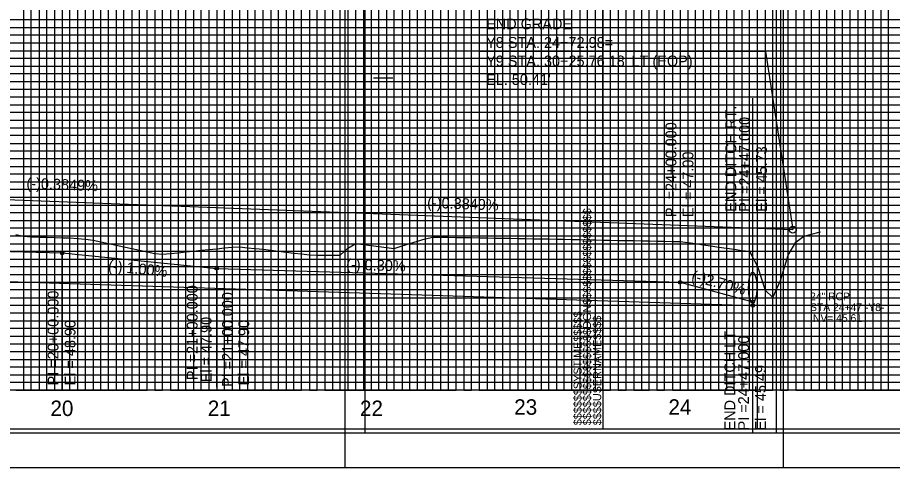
# Model space of a CAD drawing. Extents: x 2345490 to 2436403, y 465165 to 573888.
# Drawn here: x 2382738 to 2383304, y 540975 to 541266 of the extents above; entities that cross this region are included whole.
import ezdxf

# ---------------------------------------------------------------- set-up
doc = ezdxf.new("R2010")
doc.units = 0
for name, color, linetype in [('Exist Vertical Profile Horizontal Axis Label Major', 7, 'Continuous'), ('Old_Level_1', 7, 'Continuous'), ('Old_Level_18', 7, 'Continuous'), ('Old_Level_2', 7, 'Continuous'), ('Old_Level_3', 7, 'Continuous'), ('Old_Level_40', 7, 'Continuous'), ('Old_Level_41', 7, 'Continuous'), ('Old_Level_42', 7, 'Continuous'), ('Old_Level_43', 7, 'Continuous'), ('Old_Level_50', 7, 'Continuous'), ('Old_Level_51', 7, 'Continuous'), ('Old_Level_52', 7, 'Continuous')]:
    doc.layers.add(name, color=color, linetype=linetype)

msp = doc.modelspace()

# ---------------------------------------------------------------- linework, layer by layer
at = {"layer": 'Old_Level_1'}
for points in [[(2382736.7988, 541125.45291), (2382741.7988, 541124.31269), (2382746.7988, 541123.91261), (2382751.7988, 541123.78471), (2382756.7988, 541123.65566), (2382761.7988, 541123.52552), (2382766.7988, 541123.39433)], [(2382766.7988, 541123.39433), (2382771.7988, 541123.26218), (2382776.7988, 541122.90649), (2382781.7988, 541122.52221), (2382786.7988, 541121.84052), (2382791.7988, 541120.73783), (2382796.7988, 541119.63854), (2382801.7988, 541118.54315), (2382806.7988, 541117.45216), (2382811.7988, 541116.36605), (2382816.7988, 541115.28532), (2382821.7988, 541114.17672), (2382826.7988, 541113.07155), (2382831.7988, 541112.65207), (2382836.7988, 541113.14818), (2382841.7988, 541113.68281), (2382846.7988, 541114.21205), (2382851.7988, 541114.73272), (2382856.7988, 541115.2446), (2382861.7988, 541115.74744), (2382866.7988, 541116.24104), (2382871.7988, 541116.72515), (2382876.7988, 541117.19956), (2382881.7988, 541117.38911), (2382886.7988, 541116.88286), (2382891.7988, 541116.39226), (2382896.7988, 541115.91864), (2382901.7988, 541115.33093), (2382906.7988, 541114.69938), (2382911.7988, 541114.07598), (2382916.7988, 541113.461), (2382921.7988, 541112.85473), (2382926.7988, 541112.25743), (2382931.7988, 541112.11719), (2382936.7988, 541112.05292), (2382941.7988, 541111.9908), (2382946.7988, 541111.98307), (2382951.7988, 541116.65561), (2382956.7988, 541119.64421), (2382961.7988, 541119.01871), (2382966.7988, 541118.37196), (2382971.7988, 541117.70426), (2382976.7988, 541117.01592), (2382981.7988, 541116.38101), (2382986.7988, 541118.01227), (2382991.7988, 541119.61425), (2382996.7988, 541121.18623), (2383001.7988, 541122.7275), (2383006.7988, 541123.69866), (2383011.7988, 541123.71017), (2383016.7988, 541123.6775), (2383021.7988, 541123.60122), (2383026.7988, 541123.52237), (2383031.7988, 541123.441), (2383036.7988, 541123.35714), (2383041.7988, 541123.27083), (2383046.7988, 541123.1821), (2383051.7988, 541123.091), (2383056.7988, 541122.99758), (2383061.7988, 541122.90186), (2383066.7988, 541122.80938), (2383071.7988, 541122.72287), (2383076.7988, 541122.63529), (2383081.7988, 541122.54668), (2383086.7988, 541122.45707), (2383091.7988, 541122.35847), (2383096.7988, 541122.23957), (2383101.7988, 541122.13262), (2383106.7988, 541122.03737), (2383111.7988, 541121.94212), (2383116.7988, 541121.84688), (2383121.7988, 541121.75163), (2383126.7988, 541121.65638), (2383131.7988, 541121.56114), (2383136.7988, 541121.46589), (2383141.7988, 541121.37064), (2383146.7988, 541121.2754), (2383151.7988, 541121.18015), (2383156.7988, 541121.0849), (2383161.7988, 541120.98965), (2383166.7988, 541120.89441), (2383171.7988, 541120.24181), (2383176.7988, 541119.51729), (2383181.7988, 541118.79276), (2383186.7988, 541118.06824), (2383191.7988, 541117.34372), (2383196.7988, 541116.61919), (2383201.7988, 541115.89467), (2383206.7988, 541115.17015), (2383211.7988, 541114.57352), (2383216.7988, 541104.6758), (2383221.7988, 541089.28992), (2383226.7988, 541084.70339), (2383231.7988, 541095.7072), (2383236.7988, 541112.14277), (2383241.7988, 541120.4894), (2383246.7988, 541124.38886), (2383251.7988, 541125.6911), (2383256.7988, 541126.94345), (2383257.7788, 541127.17918)]]:
    msp.add_lwpolyline(points, dxfattribs=at)
at = {"layer": 'Old_Level_18'}
msp.add_line((2383116.79875, 540999.5045), (2383116.79875, 540999.5045), dxfattribs=at)
msp.add_line((2383116.79875, 540999.5045), (2383116.79875, 540999.5045), dxfattribs=at)
for points in [[(2383216.79875, 542049.5045), (2381716.79875, 542049.5045), (2381716.79875, 540999.5045), (2383216.79875, 540999.5045)], [(2384616.79875, 542049.5045), (2383116.79875, 542049.5045), (2383116.79875, 540999.5045), (2384616.79875, 540999.5045)]]:
    msp.add_lwpolyline(points, close=True, dxfattribs=at)
at = {"layer": 'Old_Level_2'}
for p, q in [((2383222.04055, 541243.91325), (2383036.88355, 541243.91325)), ((2383222.04055, 541243.91325), (2383239.77875, 541128.6045)), ((2382716.7988, 541148.60356), (2383239.77875, 541128.6045))]:
    msp.add_line(p, q, dxfattribs=at)
msp.add_circle((2383239.77875, 541128.6045), 2.25, dxfattribs=at)
at = {"layer": 'Old_Level_3'}
for p, q in [((2383166.7988, 541210.1541), (2383166.7988, 541094.5045)), ((2383213.7988, 541081.8045), (2383213.7988, 541213.67542)), ((2382666.7988, 541116.5045), (2382766.7988, 541113.5045)), ((2382766.7988, 541024.3491), (2382766.7988, 541113.5045)), ((2382766.7988, 541113.5045), (2382866.7988, 541103.5045)), ((2382316.79909, 541108.4045), (2383213.7988, 541079.4045)), ((2382866.7988, 541026.4958), (2382866.7988, 541103.5045)), ((2382866.7988, 541103.5045), (2383166.7988, 541094.5045)), ((2383166.7988, 541094.5045), (2383213.7988, 541081.8045)), ((2383213.7988, 540997.24227), (2383213.7988, 541079.4045))]:
    msp.add_line(p, q, dxfattribs=at)
for centre in [(2382766.7988, 541113.5045), (2382866.7988, 541103.5045), (2383166.7988, 541094.5045), (2383213.7988, 541081.8045), (2383213.7988, 541079.4045)]:
    msp.add_circle(centre, 1.12602, dxfattribs=at)
msp.add_ellipse((2383213.7988, 541091.1045), major_axis=(0, -10), ratio=0.264816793, dxfattribs=at)
at = {"layer": 'Old_Level_40'}
msp.add_line((2383116.79875, 540999.5045), (2383116.79875, 540999.5045), dxfattribs=at)
msp.add_line((2383116.79875, 540999.5045), (2383116.79875, 540999.5045), dxfattribs=at)
msp.add_line((2383116.79875, 540999.5045), (2383116.79875, 540999.5045), dxfattribs=at)
msp.add_line((2383116.79875, 540999.5045), (2383116.79875, 540999.5045), dxfattribs=at)
at = {"layer": 'Old_Level_41'}
for p, q in [((2382968.29875, 541227.0045), (2382980.79875, 541227.0045)), ((2383216.79875, 541024.5045), (2381716.79875, 541024.5045)), ((2384616.79875, 541024.5045), (2383116.79875, 541024.5045))]:
    msp.add_line(p, q, dxfattribs=at)
for points in [[(2382691.79875, 542049.5045), (2382741.79875, 542049.5045), (2382741.79875, 541024.5045), (2382791.79875, 541024.5045), (2382791.79875, 542049.5045), (2382841.79875, 542049.5045), (2382841.79875, 541024.5045), (2382891.79875, 541024.5045), (2382891.79875, 542049.5045), (2382941.79875, 542049.5045), (2382941.79875, 541024.5045), (2382991.79875, 541024.5045), (2382991.79875, 542049.5045)], [(2382716.79875, 542049.5045), (2382766.79875, 542049.5045), (2382766.79875, 541024.5045), (2382816.79875, 541024.5045), (2382816.79875, 542049.5045), (2382866.79875, 542049.5045), (2382866.79875, 541024.5045), (2382916.79875, 541024.5045), (2382916.79875, 542049.5045), (2382966.79875, 542049.5045), (2382966.79875, 541024.5045), (2383016.79875, 541024.5045), (2383016.79875, 542049.5045), (2383043.09875, 542049.5045)], [(2383116.79875, 542049.5045), (2383166.79875, 542049.5045), (2383166.79875, 541024.5045), (2383216.79875, 541024.5045), (2383216.79875, 542049.5045), (2383266.79875, 542049.5045), (2383266.79875, 541024.5045), (2383316.79875, 541024.5045), (2383316.79875, 542049.5045), (2383366.79875, 542049.5045), (2383366.79875, 541024.5045), (2383416.79875, 541024.5045), (2383416.79875, 542049.5045), (2383466.79875, 542049.5045), (2383466.79875, 541024.5045), (2383516.79875, 541024.5045), (2383516.79875, 542049.5045), (2383566.79875, 542049.5045), (2383566.79875, 541024.5045), (2383616.79875, 541024.5045), (2383616.79875, 542049.5045), (2383666.79875, 542049.5045), (2383666.79875, 541024.5045), (2383716.79875, 541024.5045)], [(2383191.79875, 541024.5045), (2383191.79875, 542049.5045), (2383241.79875, 542049.5045), (2383241.79875, 541024.5045), (2383291.79875, 541024.5045), (2383291.79875, 542049.5045), (2383341.79875, 542049.5045), (2383341.79875, 541024.5045), (2383391.79875, 541024.5045), (2383391.79875, 542049.5045), (2383441.79875, 542049.5045), (2383441.79875, 541024.5045), (2383491.79875, 541024.5045), (2383491.79875, 542049.5045), (2383541.79875, 542049.5045), (2383541.79875, 541024.5045), (2383591.79875, 541024.5045), (2383591.79875, 542049.5045), (2383641.79875, 542049.5045), (2383641.79875, 541024.5045), (2383691.79875, 541024.5045), (2383691.79875, 542049.5045), (2383741.79875, 542049.5045)], [(2383041.79875, 541911.9545), (2383041.79875, 541024.5045), (2383091.79875, 541024.5045), (2383091.79875, 541911.9545)], [(2383141.79875, 541911.9545), (2383141.79875, 541024.5045)], [(2383216.79875, 541249.5045), (2381716.79875, 541249.5045), (2381716.79875, 541199.5045), (2383216.79875, 541199.5045)], [(2384616.79875, 541249.5045), (2383116.79875, 541249.5045), (2383116.79875, 541199.5045), (2384616.79875, 541199.5045)], [(2383216.79875, 541149.5045), (2381716.79875, 541149.5045), (2381716.79875, 541099.5045), (2383216.79875, 541099.5045)], [(2384616.79875, 541149.5045), (2383116.79875, 541149.5045), (2383116.79875, 541099.5045), (2384616.79875, 541099.5045)], [(2383216.79875, 541074.5045), (2381716.79875, 541074.5045), (2381716.79875, 541124.5045), (2383216.79875, 541124.5045)], [(2384616.79875, 541074.5045), (2383116.79875, 541074.5045), (2383116.79875, 541124.5045), (2384616.79875, 541124.5045)], [(2383216.79875, 541049.5045), (2381716.79875, 541049.5045)], [(2384616.79875, 541049.5045), (2383116.79875, 541049.5045)], [(2383154.29875, 540999.5045), (2383154.29875, 540999.5045)]]:
    msp.add_lwpolyline(points, dxfattribs=at)
at = {"layer": 'Old_Level_42'}
for points in [[(2383066.79875, 541911.9545), (2383066.79875, 541024.5045), (2383116.79875, 541024.5045), (2383116.79875, 541911.9545)], [(2383166.79875, 541911.9545), (2383166.79875, 541024.5045), (2383216.79875, 541024.5045)], [(2383216.79875, 541174.5045), (2381716.79875, 541174.5045), (2381716.79875, 541224.5045), (2383216.79875, 541224.5045)], [(2384616.79875, 541174.5045), (2383116.79875, 541174.5045), (2383116.79875, 541224.5045), (2384616.79875, 541224.5045)]]:
    msp.add_lwpolyline(points, dxfattribs=at)
at = {"layer": 'Old_Level_43'}
for points in [[(2382736.79875, 541024.5045), (2382746.79875, 541024.5045), (2382746.79875, 542049.5045), (2382751.79875, 542049.5045), (2382751.79875, 541024.5045), (2382756.79875, 541024.5045), (2382756.79875, 542049.5045), (2382761.79875, 542049.5045), (2382761.79875, 541024.5045), (2382771.79875, 541024.5045), (2382771.79875, 542049.5045), (2382776.79875, 542049.5045), (2382776.79875, 541024.5045), (2382781.79875, 541024.5045), (2382781.79875, 542049.5045), (2382786.79875, 542049.5045), (2382786.79875, 541024.5045)], [(2382786.79875, 541024.5045), (2382796.79875, 541024.5045), (2382796.79875, 542049.5045)], [(2382801.79875, 542049.5045), (2382801.79875, 541024.5045), (2382806.79875, 541024.5045), (2382806.79875, 542049.5045)], [(2382811.79875, 542049.5045), (2382811.79875, 541024.5045), (2382821.79875, 541024.5045), (2382821.79875, 542049.5045)], [(2382826.79875, 542049.5045), (2382826.79875, 541024.5045), (2382831.79875, 541024.5045), (2382831.79875, 542049.5045)], [(2382836.79875, 542049.5045), (2382836.79875, 541024.5045), (2382846.79875, 541024.5045), (2382846.79875, 542049.5045)], [(2382851.79875, 542049.5045), (2382851.79875, 541024.5045), (2382856.79875, 541024.5045), (2382856.79875, 542049.5045)], [(2382861.79875, 542049.5045), (2382861.79875, 541024.5045), (2382871.79875, 541024.5045), (2382871.79875, 542049.5045)], [(2382876.79875, 542049.5045), (2382876.79875, 541024.5045), (2382881.79875, 541024.5045), (2382881.79875, 542049.5045)], [(2382886.79875, 542049.5045), (2382886.79875, 541024.5045), (2382896.79875, 541024.5045), (2382896.79875, 542049.5045)], [(2382901.79875, 542049.5045), (2382901.79875, 541024.5045), (2382906.79875, 541024.5045), (2382906.79875, 542049.5045)], [(2382911.79875, 542049.5045), (2382911.79875, 541024.5045), (2382921.79875, 541024.5045), (2382921.79875, 542049.5045)], [(2382926.79875, 542049.5045), (2382926.79875, 541024.5045), (2382931.79875, 541024.5045), (2382931.79875, 542049.5045)], [(2382936.79875, 542049.5045), (2382936.79875, 541024.5045), (2382946.79875, 541024.5045), (2382946.79875, 542049.5045)], [(2382951.79875, 542049.5045), (2382951.79875, 541024.5045), (2382956.79875, 541024.5045), (2382956.79875, 542049.5045)], [(2382961.79875, 542049.5045), (2382961.79875, 541024.5045), (2382971.79875, 541024.5045), (2382971.79875, 542049.5045)], [(2382976.79875, 542049.5045), (2382976.79875, 541024.5045), (2382981.79875, 541024.5045), (2382981.79875, 542049.5045)], [(2382986.79875, 542049.5045), (2382986.79875, 541024.5045), (2382996.79875, 541024.5045), (2382996.79875, 542049.5045)], [(2383001.79875, 542049.5045), (2383001.79875, 541024.5045), (2383006.79875, 541024.5045), (2383006.79875, 542049.5045)], [(2383011.79875, 542049.5045), (2383011.79875, 541024.5045), (2383021.79875, 541024.5045), (2383021.79875, 541911.9545)], [(2383171.79875, 542049.5045), (2383171.79875, 541024.5045), (2383176.79875, 541024.5045), (2383176.79875, 542049.5045)], [(2383181.79875, 542049.5045), (2383181.79875, 541024.5045), (2383186.79875, 541024.5045), (2383186.79875, 542049.5045)], [(2383196.79875, 542049.5045), (2383196.79875, 541024.5045), (2383201.79875, 541024.5045), (2383201.79875, 542049.5045)], [(2383206.79875, 542049.5045), (2383206.79875, 541024.5045), (2383211.79875, 541024.5045), (2383211.79875, 542049.5045)], [(2383221.79875, 542049.5045), (2383221.79875, 541024.5045), (2383226.79875, 541024.5045), (2383226.79875, 542049.5045)], [(2383231.79875, 542049.5045), (2383231.79875, 541024.5045), (2383236.79875, 541024.5045), (2383236.79875, 542049.5045)], [(2383246.79875, 542049.5045), (2383246.79875, 541024.5045), (2383251.79875, 541024.5045), (2383251.79875, 542049.5045)], [(2383256.79875, 542049.5045), (2383256.79875, 541024.5045), (2383261.79875, 541024.5045), (2383261.79875, 542049.5045)], [(2383271.79875, 542049.5045), (2383271.79875, 541024.5045), (2383276.79875, 541024.5045), (2383276.79875, 542049.5045)], [(2383281.79875, 542049.5045), (2383281.79875, 541024.5045), (2383286.79875, 541024.5045), (2383286.79875, 542049.5045)], [(2383296.79875, 542049.5045), (2383296.79875, 541024.5045), (2383301.79875, 541024.5045), (2383301.79875, 542049.5045)], [(2383026.79875, 541911.9545), (2383026.79875, 541024.5045), (2383031.79875, 541024.5045), (2383031.79875, 541911.9545)], [(2383036.79875, 541911.9545), (2383036.79875, 541024.5045), (2383046.79875, 541024.5045), (2383046.79875, 541911.9545)], [(2383051.79875, 541911.9545), (2383051.79875, 541024.5045), (2383056.79875, 541024.5045), (2383056.79875, 541911.9545)], [(2383061.79875, 541911.9545), (2383061.79875, 541024.5045), (2383071.79875, 541024.5045), (2383071.79875, 541911.9545)], [(2383076.79875, 541911.9545), (2383076.79875, 541024.5045), (2383081.79875, 541024.5045), (2383081.79875, 541911.9545)], [(2383086.79875, 541911.9545), (2383086.79875, 541024.5045), (2383096.79875, 541024.5045), (2383096.79875, 541911.9545)], [(2383101.79875, 541911.9545), (2383101.79875, 541024.5045)], [(2383101.79875, 541024.5045), (2383106.79875, 541024.5045), (2383106.79875, 541911.9545)], [(2383111.79875, 541911.9545), (2383111.79875, 541024.5045), (2383121.79875, 541024.5045), (2383121.79875, 541911.9545)], [(2383126.79875, 541911.9545), (2383126.79875, 541024.5045), (2383131.79875, 541024.5045), (2383131.79875, 541911.9545)], [(2383136.79875, 541911.9545), (2383136.79875, 541024.5045), (2383146.79875, 541024.5045), (2383146.79875, 541911.9545)], [(2383151.79875, 541911.9545), (2383151.79875, 541024.5045), (2383156.79875, 541024.5045), (2383156.79875, 541911.9545)], [(2383161.79875, 541911.9545), (2383161.79875, 541024.5045), (2383171.79875, 541024.5045)], [(2383166.79875, 541264.5045), (2381766.79875, 541264.5045), (2381766.79875, 541259.5045), (2383166.79875, 541259.5045)], [(2384566.79875, 541264.5045), (2383166.79875, 541264.5045), (2383166.79875, 541259.5045), (2384566.79875, 541259.5045)], [(2383166.79875, 541254.5045), (2381766.79875, 541254.5045), (2381766.79875, 541244.5045), (2383166.79875, 541244.5045)], [(2384566.79875, 541254.5045), (2383166.79875, 541254.5045), (2383166.79875, 541244.5045), (2384566.79875, 541244.5045)], [(2383166.79875, 541239.5045), (2381766.79875, 541239.5045), (2381766.79875, 541234.5045), (2383166.79875, 541234.5045)], [(2384566.79875, 541239.5045), (2383166.79875, 541239.5045), (2383166.79875, 541234.5045), (2384566.79875, 541234.5045)], [(2383166.79875, 541229.5045), (2381766.79875, 541229.5045)], [(2384566.79875, 541229.5045), (2383166.79875, 541229.5045)], [(2381766.79875, 541219.5045), (2383166.79875, 541219.5045)], [(2383166.79875, 541219.5045), (2384566.79875, 541219.5045)], [(2383166.79875, 541214.5045), (2381766.79875, 541214.5045), (2381766.79875, 541209.5045), (2383166.79875, 541209.5045)], [(2384566.79875, 541214.5045), (2383166.79875, 541214.5045), (2383166.79875, 541209.5045), (2384566.79875, 541209.5045)], [(2383166.79875, 541204.5045), (2381766.79875, 541204.5045)], [(2384566.79875, 541204.5045), (2383166.79875, 541204.5045)], [(2381766.79875, 541194.5045), (2383166.79875, 541194.5045)], [(2383166.79875, 541194.5045), (2384566.79875, 541194.5045)], [(2383166.79875, 541189.5045), (2381766.79875, 541189.5045), (2381766.79875, 541184.5045), (2383166.79875, 541184.5045)], [(2384566.79875, 541189.5045), (2383166.79875, 541189.5045), (2383166.79875, 541184.5045), (2384566.79875, 541184.5045)], [(2383166.79875, 541179.5045), (2381766.79875, 541179.5045), (2381766.79875, 541169.5045), (2383166.79875, 541169.5045)], [(2384566.79875, 541179.5045), (2383166.79875, 541179.5045), (2383166.79875, 541169.5045), (2384566.79875, 541169.5045)], [(2383166.79875, 541164.5045), (2381766.79875, 541164.5045), (2381766.79875, 541159.5045), (2383166.79875, 541159.5045)], [(2384566.79875, 541164.5045), (2383166.79875, 541164.5045), (2383166.79875, 541159.5045), (2384566.79875, 541159.5045)], [(2383166.79875, 541154.5045), (2381766.79875, 541154.5045), (2381766.79875, 541144.5045), (2383166.79875, 541144.5045)], [(2384566.79875, 541154.5045), (2383166.79875, 541154.5045), (2383166.79875, 541144.5045), (2384566.79875, 541144.5045)], [(2383166.79875, 541139.5045), (2381766.79875, 541139.5045), (2381766.79875, 541134.5045), (2383166.79875, 541134.5045)], [(2384566.79875, 541139.5045), (2383166.79875, 541139.5045), (2383166.79875, 541134.5045), (2384566.79875, 541134.5045)], [(2383166.79875, 541129.5045), (2381766.79875, 541129.5045), (2381766.79875, 541119.5045), (2383166.79875, 541119.5045)], [(2384566.79875, 541129.5045), (2383166.79875, 541129.5045), (2383166.79875, 541119.5045), (2384566.79875, 541119.5045)], [(2383166.79875, 541114.5045), (2381766.79875, 541114.5045), (2381766.79875, 541109.5045), (2383166.79875, 541109.5045)], [(2384566.79875, 541114.5045), (2383166.79875, 541114.5045), (2383166.79875, 541109.5045), (2384566.79875, 541109.5045)], [(2383166.79875, 541104.5045), (2381766.79875, 541104.5045), (2381766.79875, 541094.5045), (2383166.79875, 541094.5045)], [(2384566.79875, 541104.5045), (2383166.79875, 541104.5045), (2383166.79875, 541094.5045), (2384566.79875, 541094.5045)], [(2383166.79875, 541089.5045), (2381766.79875, 541089.5045), (2381766.79875, 541084.5045), (2383166.79875, 541084.5045)], [(2384566.79875, 541089.5045), (2383166.79875, 541089.5045), (2383166.79875, 541084.5045), (2384566.79875, 541084.5045)], [(2383166.79875, 541079.5045), (2381766.79875, 541079.5045), (2381766.79875, 541069.5045), (2383166.79875, 541069.5045)], [(2384566.79875, 541079.5045), (2383166.79875, 541079.5045), (2383166.79875, 541069.5045), (2384566.79875, 541069.5045)], [(2383166.79875, 541064.5045), (2381766.79875, 541064.5045), (2381766.79875, 541059.5045), (2383166.79875, 541059.5045)], [(2384566.79875, 541064.5045), (2383166.79875, 541064.5045), (2383166.79875, 541059.5045), (2384566.79875, 541059.5045)], [(2383166.79875, 541054.5045), (2381766.79875, 541054.5045), (2381766.79875, 541044.5045), (2383166.79875, 541044.5045)], [(2384566.79875, 541054.5045), (2383166.79875, 541054.5045), (2383166.79875, 541044.5045), (2384566.79875, 541044.5045)], [(2383166.79875, 541039.5045), (2381766.79875, 541039.5045), (2381766.79875, 541034.5045), (2383166.79875, 541034.5045)], [(2384566.79875, 541039.5045), (2383166.79875, 541039.5045), (2383166.79875, 541034.5045), (2384566.79875, 541034.5045)], [(2383166.79875, 541029.5045), (2381766.79875, 541029.5045)], [(2384566.79875, 541029.5045), (2383166.79875, 541029.5045)]]:
    msp.add_lwpolyline(points, dxfattribs=at)
at = {"layer": 'Old_Level_50'}
msp.add_line((2382949.79875, 540974.5045), (2382949.79875, 540974.5045), dxfattribs=at)
for points in [[(2383229.29875, 542052.0545), (2381562.79875, 542052.0545), (2381562.79875, 540996.9545), (2383229.29875, 540996.9545)], [(2384629.29875, 542052.0545), (2382962.79875, 542052.0545), (2382962.79875, 540996.9545), (2384629.29875, 540996.9545)]]:
    msp.add_lwpolyline(points, close=True, dxfattribs=at)
at = {"layer": 'Old_Level_51'}
for points in [[(2383233.79875, 542074.5045), (2381549.79875, 542074.5045), (2381549.79875, 540974.5045), (2383233.79875, 540974.5045)], [(2384633.79875, 542074.5045), (2382949.79875, 542074.5045), (2382949.79875, 540974.5045), (2384633.79875, 540974.5045)]]:
    msp.add_lwpolyline(points, close=True, dxfattribs=at)
at = {"layer": 'Old_Level_52'}
msp.add_line((2382962.79875, 540996.9545), (2382962.79875, 540996.9545), dxfattribs=at)

# ---------------------------------------------------------------- texts
at = {"layer": 'Exist Vertical Profile Horizontal Axis Label Major'}
for s, p in [('20', (2382759.18516, 541007.86924)), ('21', (2382861.02456, 541007.86924)), ('22', (2382959.57304, 541007.86924)), ('23', (2383059.40789, 541008.69864)), ('24', (2383159.25031, 541008.69864))]:
    msp.add_text(s, height=10.000001, dxfattribs=at).set_placement(p)
at = {"layer": 'Old_Level_2'}
for s, height, p in [('END GRADE', 7.000001, (2383041.2238, 541258.36625)), ('Y8 STA. 24+72.98=', 7.0000005, (2383041.2238, 541246.36625)), ("Y9 STA. 30+25.76 18' LT (EOP)", 7.0000005, (2383041.2238, 541234.36625)), ("EL. 50.41' ", 7.0000005, (2383041.2238, 541222.36625))]:
    msp.add_text(s, height=height, dxfattribs=at).set_placement(p)
for p in [(2382743.55696, 541155.28903), (2383002.94472, 541142.81846)]:
    msp.add_text('(-)0.3849%', height=7, rotation=357.7471697, dxfattribs=at).set_placement(p)
at = {"layer": 'Old_Level_3'}
for s, height, rotation, p in [('END DITCH RT.', 7.0000005, 90, (2383203.14605, 541140.21463)), ('PI =24+00.000', 7.0000005, 90, (2383164.3938, 541136.7485)), ('PI =24+47.000', 7.0000005, 90, (2383212.01995, 541140.21463)), ('El = 45.73', 7.000001, 90, (2383223.01995, 541140.21463)), ('El = 47.00', 7.000001, 90, (2383175.3938, 541136.7485)), ('(-) 1.00%', 7.000001, 354.2894069, (2382796.2421, 541101.80852)), ('(-) 0.30%', 7.000001, 358.281642, (2382950.56263, 541102.6779)), ('(-)2.70%', 7.000001, 344.8790632, (2383173.65627, 541095.56937)), ('PI =21+00.000', 7.0000005, 90, (2382854.45902, 541031.17004)), ('PI =20+00.000', 7.0000005, 90, (2382764.3938, 541027.67534)), ('PI =21+00.000', 7.0000005, 90, (2382877.30902, 541026.69938)), ('El = 48.90', 7.000001, 90, (2382775.3938, 541027.67534)), ('El = 47.90', 7.000001, 90, (2382863.47206, 541029.67982)), ('El = 47.90', 7.000001, 90, (2382887.81228, 541027.69286)), ('END DITCH LT', 7.0000005, 90, (2383202.5199, 540998.50801)), ('PI =24+47.000', 7.0000005, 90, (2383211.3938, 540998.50801)), ('El = 45.49', 7.000001, 90, (2383222.3938, 540998.50801))]:
    msp.add_text(s, height=height, rotation=rotation, dxfattribs=at).set_placement(p)
for s, height, p in [('24" RCP', 4.999999, (2383250.93388, 541082.8386)), ('STA 24+47 -Y8-', 4.9999995, (2383250.93388, 541075.8386)), ('INV= 45.61', 4.999999, (2383250.93388, 541068.83861))]:
    msp.add_text(s, height=height, dxfattribs=at).set_placement(p)
at = {"layer": 'Old_Level_41'}
for s, p in [('$$$$$$$$$$$$$$$$DGN$$$$$$$$$$$$$$$$', (2383109.14875, 541001.867)), ('$$$$$$SYSTIME$$$$$', (2383103.09875, 541001.867)), ('$$$$USERNAME$$$$', (2383115.72375, 541001.8795))]:
    msp.add_text(s, height=5.25, rotation=90, dxfattribs=at).set_placement(p)

doc.saveas('drawing.dxf')
